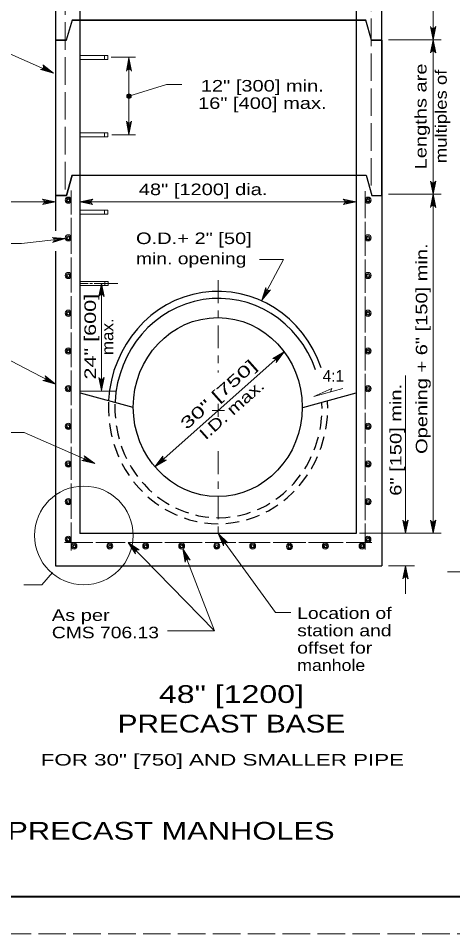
# Model space of a CAD drawing. Extents: x 808.4 to 842.4, y 1034.6 to 1056.6.
# Drawn here: x 819.97 to 825.84, y 1034.63 to 1047.01 of the extents above; entities that cross this region are included whole.
import ezdxf
from ezdxf.enums import TextEntityAlignment as Align

# ---------------------------------------------------------------- set-up
doc = ezdxf.new("R2010")
doc.units = 0
doc.header["$LTSCALE"] = 0.062
for name, pattern in [('DOT_DASHED', [7.7, 5, -1.2, 0.3, -1.2]), ('LONG_DASHED', [7.5, 6, -1.5]), ('MEDIUM_DASHED', [4.5, 3, -1.5])]:
    doc.linetypes.add(name, pattern=pattern)
doc.layers.add('1', color=7, linetype='Continuous', lineweight=13)
doc.layers.add('10', color=7, linetype='Continuous')

msp = doc.modelspace()

# ---------------------------------------------------------------- hatches: boundary and pattern name
at = {"layer": '1'}
msp.add_hatch(color=256, dxfattribs=at).paths.add_polyline_path([(821.49358, 1045.95525, 1), (821.43458, 1045.95525, 1)])

# ---------------------------------------------------------------- linework, layer by layer
at = {"layer": '1', "lineweight": 25}
for p, q in [((820.7995, 1049.0825), (820.7995, 1040.04192)), ((824.53808, 1049.0825), (824.53808, 1040.04192)), ((820.47083, 1048.75375), (820.47083, 1046.71117)), ((824.8835, 1046.71117), (824.88358, 1048.75375)), ((820.6975, 1046.98442), (824.66817, 1046.98442)), ((820.47083, 1046.71117), (820.47083, 1044.13583)), ((820.47083, 1046.71117), (820.61992, 1046.71117)), ((824.74583, 1046.71117), (824.88125, 1046.71117)), ((824.75008, 1046.71117), (824.88358, 1046.71117)), ((824.75008, 1046.71117), (824.8835, 1046.71117)), ((824.88358, 1046.71117), (824.88358, 1039.60358)), ((820.6975, 1044.88633), (824.6725, 1044.88633)), ((820.47083, 1043.85758), (820.47083, 1039.60358)), ((821.52008, 1041.74633), (820.80675, 1041.93983)), ((823.814, 1041.74633), (824.5355, 1041.942)), ((824.53942, 1040.04192), (820.7995, 1040.04192)), ((820.98625, 1040.04192), (820.7995, 1040.04192)), ((820.47083, 1039.60358), (824.88358, 1039.60358))]:
    msp.add_line(p, q, dxfattribs=at)
at = {"layer": '1', "linetype": 'LONG_DASHED'}
for p, q in [((824.74183, 1048.89308), (824.74183, 1044.64242)), ((820.59942, 1048.84225), (820.59942, 1044.61292))]:
    msp.add_line(p, q, dxfattribs=at)
at = {"layer": '1'}
for p, q in [((825.5775, 1048.75675), (825.5775, 1046.73775)), ((820.69325, 1046.98442), (820.61567, 1046.71117)), ((825.55508, 1046.87925), (825.5775, 1046.719)), ((825.56617, 1046.87383), (825.5775, 1046.719)), ((825.60233, 1046.88117), (825.5775, 1046.719)), ((825.59192, 1046.875), (825.5775, 1046.719)), ((825.5775, 1046.87217), (825.5775, 1046.719)), ((825.5775, 1046.80608), (825.5775, 1046.73242)), ((820.61625, 1046.71117), (820.48017, 1046.71117)), ((824.97292, 1046.71808), (825.68708, 1046.71808)), ((824.97292, 1046.71808), (825.68708, 1046.71808)), ((824.97292, 1046.71808), (825.68708, 1046.71808)), ((825.55275, 1046.55625), (825.5775, 1046.71833)), ((825.56317, 1046.56233), (825.5775, 1046.71833)), ((825.5775, 1046.56517), (825.5775, 1046.71833)), ((825.58883, 1046.56358), (825.5775, 1046.71833)), ((825.59992, 1046.55817), (825.5775, 1046.71833)), ((825.5775, 1046.70792), (825.5775, 1044.64733)), ((820.79992, 1046.50367), (821.178, 1046.50367)), ((820.79992, 1046.45058), (821.178, 1046.45058)), ((821.13425, 1046.4505), (821.13425, 1046.5035)), ((821.178, 1046.45058), (821.178, 1046.50367)), ((821.22425, 1046.48117), (821.553, 1046.48117)), ((821.43933, 1046.30958), (821.46408, 1046.47175)), ((821.44967, 1046.31575), (821.46408, 1046.47175)), ((821.46408, 1046.47175), (821.46408, 1045.43875)), ((821.46408, 1046.31858), (821.46408, 1046.47175)), ((821.47542, 1046.31692), (821.46408, 1046.47175)), ((821.4865, 1046.3115), (821.46408, 1046.47175)), ((820.28617, 1046.31842), (820.44242, 1046.26842)), ((820.29633, 1046.325), (820.44242, 1046.26842)), ((820.30525, 1046.33658), (820.44242, 1046.26842)), ((820.30883, 1046.3475), (820.44242, 1046.26842)), ((820.30892, 1046.35983), (820.44242, 1046.26842)), ((821.44167, 1045.599), (821.46408, 1045.43875)), ((821.45275, 1045.59358), (821.46408, 1045.43875)), ((821.48883, 1045.60092), (821.46408, 1045.43875)), ((821.4785, 1045.59475), (821.46408, 1045.43875)), ((821.46408, 1045.59192), (821.46408, 1045.43875)), ((820.79992, 1045.45742), (821.178, 1045.45742)), ((821.13425, 1045.40442), (821.13425, 1045.45742)), ((821.178, 1045.4045), (821.178, 1045.45742)), ((821.2325, 1045.43267), (821.553, 1045.43267)), ((820.79992, 1045.4045), (821.178, 1045.4045)), ((820.682, 1044.68158), (820.682, 1044.357)), ((825.55508, 1044.78883), (825.5775, 1044.62858)), ((825.56617, 1044.78342), (825.5775, 1044.62858)), ((825.60233, 1044.79075), (825.5775, 1044.62858)), ((825.59192, 1044.78458), (825.5775, 1044.62858)), ((825.5775, 1044.78175), (825.5775, 1044.62858)), ((820.62058, 1044.61308), (820.48442, 1044.61308)), ((824.65792, 1044.67175), (824.65792, 1044.30392)), ((824.74942, 1044.61308), (824.88358, 1044.61308)), ((824.97292, 1044.62767), (825.68708, 1044.62767)), ((825.55275, 1044.466), (825.5775, 1044.62817)), ((825.56317, 1044.47217), (825.5775, 1044.62817)), ((825.5775, 1044.475), (825.5775, 1044.62817)), ((825.58883, 1044.47333), (825.5775, 1044.62817)), ((825.59992, 1044.46792), (825.5775, 1044.62817)), ((825.5775, 1044.62767), (825.5775, 1040.04517)), ((820.47083, 1044.52517), (818.43792, 1044.52517)), ((820.30867, 1044.50042), (820.47083, 1044.52517)), ((820.31058, 1044.54758), (820.47083, 1044.52517)), ((820.31483, 1044.51083), (820.47083, 1044.52517)), ((820.316, 1044.5365), (820.47083, 1044.52517)), ((820.31767, 1044.52517), (820.47083, 1044.52517)), ((820.95975, 1044.54758), (820.7995, 1044.52517)), ((820.95433, 1044.5365), (820.7995, 1044.52517)), ((820.7995, 1044.52517), (823.3355, 1044.52517)), ((820.95267, 1044.52517), (820.7995, 1044.52517)), ((820.9555, 1044.51083), (820.7995, 1044.52517)), ((820.96158, 1044.50042), (820.7995, 1044.52517)), ((823.3355, 1044.52517), (824.53808, 1044.52517)), ((824.376, 1044.50042), (824.53808, 1044.52517)), ((824.37783, 1044.54758), (824.53808, 1044.52517)), ((824.38208, 1044.51083), (824.53808, 1044.52517)), ((824.38333, 1044.5365), (824.53808, 1044.52517)), ((824.38492, 1044.52517), (824.53808, 1044.52517)), ((820.682, 1044.30783), (820.682, 1043.82433)), ((820.79992, 1044.41125), (821.178, 1044.41125)), ((820.79992, 1044.35842), (821.178, 1044.35842)), ((821.13425, 1044.35858), (821.13425, 1044.4115)), ((821.178, 1044.35842), (821.178, 1044.41125)), ((824.65792, 1044.25475), (824.65792, 1043.79575)), ((820.43917, 1044.03683), (820.60308, 1044.0305)), ((820.44642, 1044.02717), (820.60308, 1044.0305)), ((820.44642, 1043.99008), (820.60308, 1044.0305)), ((820.4505, 1044.00175), (820.60308, 1044.0305)), ((820.45092, 1044.01317), (820.60308, 1044.0305)), ((820.682, 1043.77525), (820.682, 1043.29992)), ((824.65792, 1043.74667), (824.65792, 1043.29583)), ((820.80267, 1043.44967), (821.18067, 1043.44967)), ((821.13617, 1043.39708), (821.13617, 1043.45008)), ((821.18067, 1043.39667), (821.18067, 1043.44967)), ((820.80017, 1043.42325), (820.91392, 1043.42325)), ((820.80267, 1043.39667), (821.18067, 1043.39667)), ((820.93358, 1043.42325), (820.97233, 1043.42325)), ((820.99267, 1043.42325), (821.31308, 1043.42325)), ((821.06692, 1043.26092), (821.09175, 1043.423)), ((821.07733, 1043.267), (821.09175, 1043.423)), ((821.09175, 1043.423), (821.09175, 1041.974)), ((821.09175, 1043.26983), (821.09175, 1043.423)), ((821.10308, 1043.26817), (821.09175, 1043.423)), ((821.11417, 1043.26275), (821.09175, 1043.423)), ((823.31883, 1043.34733), (823.26333, 1043.19542)), ((823.32608, 1043.33733), (823.26333, 1043.19542)), ((823.33533, 1043.33058), (823.26333, 1043.19542)), ((823.36142, 1043.32683), (823.26333, 1043.19542)), ((823.34933, 1043.32633), (823.26333, 1043.19542)), ((820.682, 1043.25075), (820.682, 1042.80817)), ((824.65792, 1043.24667), (824.65792, 1042.75908)), ((820.682, 1042.75908), (820.682, 1042.29192)), ((824.65792, 1042.70992), (824.65792, 1042.24683)), ((821.81508, 1040.94158), (823.56483, 1042.49608)), ((823.42667, 1042.40767), (823.56483, 1042.49608)), ((823.43808, 1042.40392), (823.56483, 1042.49608)), ((823.44975, 1042.395), (823.56483, 1042.49608)), ((823.456, 1042.38533), (823.56483, 1042.49608)), ((823.45925, 1042.3735), (823.56483, 1042.49608)), ((820.682, 1042.24275), (820.682, 1041.77558)), ((820.31567, 1042.11167), (820.47083, 1042.05842)), ((820.32592, 1042.11808), (820.47083, 1042.05842)), ((820.33508, 1042.1295), (820.47083, 1042.05842)), ((820.33892, 1042.14033), (820.47083, 1042.05842)), ((820.33925, 1042.15267), (820.47083, 1042.05842)), ((821.06933, 1042.13425), (821.09175, 1041.974)), ((821.08042, 1042.12883), (821.09175, 1041.974)), ((821.1165, 1042.13617), (821.09175, 1041.974)), ((821.10608, 1042.13), (821.09175, 1041.974)), ((821.09175, 1042.12717), (821.09175, 1041.974)), ((824.65792, 1042.19767), (824.65792, 1041.72233)), ((825.20375, 1042.17908), (825.20375, 1040.04517)), ((820.81275, 1041.96708), (821.29075, 1041.96708)), ((823.96317, 1041.8935), (824.35825, 1042.00075)), ((820.682, 1041.7265), (820.682, 1041.26342)), ((822.58808, 1041.70475), (822.75533, 1041.70475)), ((822.67242, 1041.793), (822.67242, 1041.61742)), ((824.65792, 1041.67317), (824.65792, 1041.25933)), ((820.682, 1041.21425), (820.682, 1040.76758)), ((824.65792, 1041.21017), (824.65792, 1040.739)), ((820.84725, 1041.03158), (821.00275, 1040.98675)), ((820.85675, 1041.0395), (821.00275, 1040.98675)), ((820.86292, 1041.04917), (821.00275, 1040.98675)), ((820.86483, 1041.07542), (821.00275, 1040.98675)), ((820.86617, 1041.0635), (821.00275, 1040.98675)), ((821.92, 1041.06475), (821.81508, 1040.94158)), ((821.92325, 1041.05283), (821.81508, 1040.94158)), ((821.92958, 1041.04333), (821.81508, 1040.94158)), ((821.94125, 1041.03442), (821.81508, 1040.94158)), ((821.95275, 1041.03075), (821.81508, 1040.94158)), ((820.682, 1040.7185), (820.682, 1040.23908)), ((824.65792, 1040.68983), (824.65792, 1040.22267)), ((820.682, 1040.18992), (820.682, 1039.80892)), ((820.7995, 1040.16242), (820.7995, 1040.04192)), ((824.65792, 1040.1735), (824.65792, 1039.82383)), ((825.18133, 1040.20542), (825.20375, 1040.04517)), ((825.1925, 1040.2), (825.20375, 1040.04517)), ((825.22858, 1040.20733), (825.20375, 1040.04517)), ((825.21817, 1040.20117), (825.20375, 1040.04517)), ((825.20375, 1040.19833), (825.20375, 1040.04517)), ((825.55508, 1040.20542), (825.5775, 1040.04517)), ((825.56617, 1040.2), (825.5775, 1040.04517)), ((825.60233, 1040.20733), (825.5775, 1040.04517)), ((825.59192, 1040.20117), (825.5775, 1040.04517)), ((825.5775, 1040.19833), (825.5775, 1040.04517)), ((822.75808, 1039.915), (822.67242, 1040.04192)), ((822.77158, 1039.92067), (822.67242, 1040.04192)), ((822.78367, 1039.92142), (822.67242, 1040.04192)), ((822.74967, 1039.90725), (822.67242, 1040.04192)), ((822.7435, 1039.89658), (822.67242, 1040.04192)), ((822.67242, 1040.04192), (823.44675, 1038.97283)), ((824.53942, 1040.04192), (824.31883, 1040.04192)), ((824.58208, 1040.04517), (825.68708, 1040.04517)), ((820.9755, 1039.91742), (820.59367, 1039.91742)), ((821.41292, 1039.91742), (821.01425, 1039.91742)), ((821.91217, 1039.91742), (821.45167, 1039.91742)), ((821.56017, 1039.80942), (821.45167, 1039.91742)), ((821.57233, 1039.81758), (821.45167, 1039.91742)), ((821.584, 1039.82067), (821.45167, 1039.91742)), ((821.55333, 1039.80017), (821.45167, 1039.91742)), ((821.54942, 1039.7885), (821.45167, 1039.91742)), ((821.45167, 1039.91742), (822.61883, 1038.722)), ((822.454, 1039.91742), (821.95083, 1039.91742)), ((822.91067, 1039.91742), (822.49267, 1039.91742)), ((823.375, 1039.91742), (822.94933, 1039.91742)), ((823.855, 1039.91742), (823.41375, 1039.91742)), ((824.362, 1039.91742), (823.89367, 1039.91742)), ((824.75017, 1039.91742), (824.40067, 1039.91742)), ((822.24908, 1039.69008), (822.19058, 1039.83167)), ((822.26342, 1039.69292), (822.19058, 1039.83167)), ((822.27542, 1039.69125), (822.19058, 1039.83167)), ((822.23925, 1039.68425), (822.19058, 1039.83167)), ((822.23108, 1039.675), (822.19058, 1039.83167)), ((824.97292, 1039.60358), (825.32475, 1039.60358)), ((825.179, 1039.4415), (825.20375, 1039.60358)), ((825.18942, 1039.44758), (825.20375, 1039.60358)), ((825.20375, 1039.60358), (825.20375, 1039.22383)), ((825.20375, 1039.45042), (825.20375, 1039.60358)), ((825.21508, 1039.44883), (825.20375, 1039.60358)), ((825.22625, 1039.44333), (825.20375, 1039.60358)), ((825.77383, 1039.52317), (827.04975, 1039.52317)), ((823.44675, 1038.97283), (823.655, 1038.97283))]:
    msp.add_line(p, q, dxfattribs=at)
at = {"layer": '1', "linetype": 'DOT_DASHED'}
for p, q in [((822.67242, 1043.4655), (822.67242, 1042.2175)), ((822.67242, 1041.15467), (822.67242, 1040.04192))]:
    msp.add_line(p, q, dxfattribs=at)
at = {"layer": '1', "linetype": 'LONG_DASHED'}
msp.add_lwpolyline([(808.43883, 1034.62767), (842.43883, 1034.62767), (842.43883, 1056.62767), (808.43883, 1056.62767)], close=True, dxfattribs=at)
at = {"layer": '1', "lineweight": 25}
for points in [[(810.43883, 1056.12767), (841.93883, 1056.12767), (841.93883, 1035.12767), (810.43883, 1035.12767)], [(820.69325, 1046.98442), (820.61567, 1046.71117), (820.47083, 1046.71117), (820.47083, 1044.61308), (820.61992, 1044.61308), (820.6975, 1044.88633), (824.6725, 1044.88633), (824.75008, 1044.61308), (824.8835, 1044.61308), (824.88358, 1046.71117), (824.74583, 1046.71117), (824.66817, 1046.98442)]]:
    msp.add_lwpolyline(points, close=True, dxfattribs=at)
at = {"layer": '1', "lineweight": 40}
msp.add_lwpolyline([(810.43883, 1056.12767), (841.93883, 1056.12767), (841.93883, 1035.12767), (810.43883, 1035.12767)], close=True, dxfattribs=at)
at = {"layer": '1', "lineweight": 25}
for points in [[(820.69325, 1046.98442), (820.61567, 1046.71117), (820.47083, 1046.71117)], [(820.6975, 1044.88633), (820.61992, 1044.61308), (820.47083, 1044.61308)], [(824.6725, 1044.88633), (824.75008, 1044.61308), (824.8835, 1044.61308)]]:
    msp.add_lwpolyline(points, dxfattribs=at)
at = {"layer": '1'}
for points in [[(825.61292, 1046.896), (825.5775, 1046.719), (825.54217, 1046.896)], [(825.54217, 1046.54133), (825.5775, 1046.71833), (825.61292, 1046.54133)], [(820.44242, 1046.26842), (819.72975, 1046.58067), (819.50075, 1046.58067)], [(821.42867, 1046.29475), (821.46408, 1046.47175), (821.4995, 1046.29475)], [(820.26817, 1046.3155), (820.44242, 1046.26842), (820.29967, 1046.37892)], [(821.46408, 1045.95525), (821.96925, 1046.11392), (822.17908, 1046.11392)], [(821.4995, 1045.61575), (821.46408, 1045.43875), (821.42867, 1045.61575)], [(825.61292, 1044.80558), (825.5775, 1044.62858), (825.54217, 1044.80558)], [(820.29383, 1044.48983), (820.47083, 1044.52517), (820.29383, 1044.56058)], [(820.9765, 1044.48983), (820.7995, 1044.52517), (820.9765, 1044.56058)], [(824.36108, 1044.48983), (824.53808, 1044.52517), (824.36108, 1044.56058)], [(825.54217, 1044.45117), (825.5775, 1044.62817), (825.61292, 1044.45117)], [(820.60308, 1044.0305), (820.01208, 1043.96475), (819.82133, 1043.96475)], [(820.42325, 1044.04567), (820.60308, 1044.0305), (820.43117, 1043.97533)], [(823.26333, 1043.19542), (823.55575, 1043.74558), (823.22758, 1043.74558)], [(821.05633, 1043.246), (821.09175, 1043.423), (821.12717, 1043.246)], [(823.37775, 1043.335), (823.26333, 1043.19542), (823.31525, 1043.36825)], [(823.4085, 1042.40583), (823.56483, 1042.49608), (823.45517, 1042.35267)], [(820.47083, 1042.05842), (819.77183, 1042.42392), (819.52642, 1042.42392)], [(820.29758, 1042.10917), (820.47083, 1042.05842), (820.33042, 1042.17192)], [(821.12717, 1042.151), (821.09175, 1041.974), (821.05633, 1042.151)], [(823.96317, 1041.8935), (824.20992, 1042.00067), (824.18925, 1041.95442)], [(821.00275, 1040.98675), (820.04792, 1041.40742), (819.70025, 1041.40742)], [(820.85558, 1041.09125), (821.00275, 1040.98675), (820.82667, 1041.02658)], [(821.97092, 1041.03267), (821.81508, 1040.94158), (821.92392, 1041.08558)], [(825.23917, 1040.22217), (825.20375, 1040.04517), (825.16842, 1040.22217)], [(825.61292, 1040.22217), (825.5775, 1040.04517), (825.54217, 1040.22217)], [(822.80075, 1039.915), (822.67242, 1040.04192), (822.74208, 1039.87542)], [(821.60208, 1039.81767), (821.45167, 1039.91742), (821.55208, 1039.7675)], [(822.19058, 1039.83167), (822.61883, 1038.722), (821.98617, 1038.722)], [(822.29092, 1039.68158), (822.19058, 1039.83167), (822.22542, 1039.6545)], [(825.16842, 1039.42658), (825.20375, 1039.60358), (825.23917, 1039.42658)], [(820.42783, 1039.51225), (820.286, 1039.34492), (820.04183, 1039.34492)]]:
    msp.add_lwpolyline(points, dxfattribs=at)
for centre, radius in [((821.46408, 1045.95525), 0.0295), ((820.85329, 1040.01429), 0.66724)]:
    msp.add_circle(centre, radius, dxfattribs=at)
for centre, start, end in [((825.5775, 1046.91031), 202.08782, 337.91395), ((825.57757, 1046.52707), 22.08782, 157.91395), ((820.27113, 1046.35362), 265.65574, 41.48187), ((821.46412, 1046.28045), 22.08782, 157.91395), ((821.46404, 1045.63005), 202.08782, 337.91395), ((825.5775, 1044.8199), 202.08782, 337.91395), ((820.27952, 1044.52524), 292.08605, 67.91218), ((820.99077, 1044.52524), 112.08782, 247.91395), ((824.34682, 1044.52524), 292.08605, 67.91218), ((825.57757, 1044.43687), 22.08782, 157.91395), ((820.41301, 1044.00885), 298.57135, 74.39748), ((823.35321, 1043.36424), 174.04908, 309.87521), ((821.09177, 1043.23171), 22.08782, 157.91395), ((823.42112, 1042.36978), 333.38681, 109.21294), ((820.30135, 1042.14721), 264.45514, 40.28127), ((821.09169, 1042.16529), 202.08782, 337.91395), ((820.82806, 1041.06468), 268.03056, 43.85669), ((821.95806, 1041.06866), 153.70609, 289.53222), ((825.20375, 1040.23649), 202.08782, 337.91395), ((825.5775, 1040.23649), 202.08782, 337.91395), ((822.77938, 1039.88333), 56.08264, 191.90876), ((821.58719, 1039.78247), 67.22478, 203.05091), ((822.26358, 1039.65481), 44.5246, 180.35073), ((825.20383, 1039.41232), 22.08782, 157.91395)]:
    msp.add_arc(centre, 0.0382, start, end, dxfattribs=at)
for centre, major_axis in [((820.64222, 1044.54877), (0, 0.04232)), ((820.64152, 1044.5471), (0, -0.02865)), ((820.64348, 1044.54469), (0, -0.01649)), ((824.69843, 1044.54877), (0, 0.04232)), ((824.69914, 1044.5471), (0, -0.02865)), ((824.69718, 1044.54469), (0, -0.01649)), ((820.64222, 1044.03906), (0, 0.04232)), ((820.64152, 1044.03739), (0, -0.02865)), ((824.69843, 1044.03906), (0, 0.04232)), ((824.69914, 1044.03739), (0, -0.02865)), ((820.64348, 1044.03498), (0, -0.01649)), ((824.69718, 1044.03498), (0, -0.01649)), ((820.64222, 1043.52935), (0, 0.04232)), ((824.69843, 1043.52935), (0, 0.04232)), ((820.64152, 1043.52769), (0, -0.02865)), ((820.64348, 1043.52527), (0, -0.01649)), ((824.69914, 1043.52769), (0, -0.02865)), ((824.69718, 1043.52527), (0, -0.01649)), ((820.64222, 1043.01965), (0, 0.04232)), ((820.64152, 1043.01798), (0, -0.02865)), ((820.64348, 1043.01557), (0, -0.01649)), ((824.69843, 1043.01965), (0, 0.04232)), ((824.69914, 1043.01798), (0, -0.02865)), ((824.69718, 1043.01557), (0, -0.01649)), ((820.64222, 1042.50994), (0, 0.04232)), ((820.64152, 1042.50828), (0, -0.02865)), ((820.64348, 1042.50586), (0, -0.01649)), ((824.69843, 1042.50994), (0, 0.04232)), ((824.69914, 1042.50828), (0, -0.02865)), ((824.69718, 1042.50586), (0, -0.01649)), ((820.64222, 1042.00023), (0, 0.04232)), ((820.64152, 1041.99857), (0, -0.02865)), ((820.64348, 1041.99615), (0, -0.01649)), ((824.69843, 1042.00023), (0, 0.04232)), ((824.69914, 1041.99857), (0, -0.02865)), ((824.69718, 1041.99615), (0, -0.01649)), ((820.64222, 1041.49053), (0, 0.04232)), ((820.64152, 1041.48886), (0, -0.02865)), ((820.64348, 1041.48645), (0, -0.01649)), ((824.69843, 1041.49053), (0, 0.04232)), ((824.69914, 1041.48886), (0, -0.02865)), ((824.69718, 1041.48645), (0, -0.01649)), ((820.64222, 1040.98082), (0, 0.04232)), ((820.64152, 1040.97916), (0, -0.02865)), ((820.64348, 1040.97674), (0, -0.01649)), ((824.69843, 1040.98082), (0, 0.04232)), ((824.69914, 1040.97916), (0, -0.02865)), ((824.69718, 1040.97674), (0, -0.01649)), ((820.64222, 1040.47112), (0, 0.04232)), ((820.64152, 1040.46945), (0, -0.02865)), ((820.64348, 1040.46703), (0, -0.01649)), ((824.69843, 1040.47112), (0, 0.04232)), ((824.69914, 1040.46945), (0, -0.02865)), ((824.69718, 1040.46703), (0, -0.01649)), ((820.64222, 1039.96141), (0, 0.04232)), ((820.64152, 1039.95974), (0, -0.02865)), ((820.64348, 1039.95733), (0, -0.01649)), ((824.69725, 1039.96141), (0, 0.04232)), ((824.69615, 1039.96174), (0, -0.02865)), ((824.69812, 1039.95933), (0, -0.01649)), ((820.72065, 1039.87113), (0, 0.04232)), ((820.72089, 1039.87071), (0, -0.02865)), ((820.72286, 1039.8683), (0, -0.01649)), ((821.2039, 1039.87113), (0, 0.04232)), ((821.20351, 1039.87071), (0, -0.02865)), ((821.20548, 1039.8683), (0, -0.01649)), ((821.69006, 1039.87113), (0, 0.04232)), ((821.68849, 1039.87071), (0, -0.02865)), ((821.69046, 1039.8683), (0, -0.01649)), ((822.17622, 1039.87113), (0, 0.04232)), ((822.17449, 1039.87071), (0, -0.02865)), ((822.17646, 1039.8683), (0, -0.01649)), ((822.6509, 1039.87113), (0, 0.04232)), ((822.65011, 1039.87005), (0, -0.02865)), ((822.65208, 1039.86763), (0, -0.01649)), ((823.13706, 1039.87113), (0, 0.04232)), ((823.13682, 1039.87129), (0, -0.02865)), ((823.13879, 1039.86888), (0, -0.01649)), ((823.63478, 1039.86505), (0, 0.04232)), ((823.63596, 1039.86446), (0, -0.02865)), ((823.63793, 1039.86205), (0, -0.01649)), ((824.12086, 1039.87113), (0, 0.04232)), ((824.12165, 1039.87079), (0, -0.02865)), ((824.12362, 1039.86838), (0, -0.01649)), ((824.61631, 1039.87263), (0, 0.04232)), ((824.61741, 1039.87338), (0, -0.02865)), ((824.61937, 1039.87096), (0, -0.01649))]:
    msp.add_ellipse(centre, major_axis=major_axis, ratio=0.944544, dxfattribs=at)
at = {"layer": '1', "lineweight": 25}
for centre, major_axis, start_param, end_param in [((822.66861, 1041.7442), (0, 1.57124), 5.05957511, 7.79178954), ((822.67458, 1041.73702), (0, 1.48364), 5.06755757, 7.79799099)]:
    msp.add_ellipse(centre, major_axis=major_axis, ratio=0.944544, start_param=start_param, end_param=end_param, dxfattribs=at)
msp.add_ellipse((822.66467, 1041.75071), major_axis=(0, 1.20985), ratio=0.944544, dxfattribs=at)
at = {"layer": '1', "linetype": 'MEDIUM_DASHED', "lineweight": 25}
for centre, major_axis, start_param, end_param in [((822.66861, 1041.7442), (0, 1.57124), 1.52605103, 4.76713962), ((822.67458, 1041.73702), (0, 1.48364), 1.53664377, 4.75717553)]:
    msp.add_ellipse(centre, major_axis=major_axis, ratio=0.944544, start_param=start_param, end_param=end_param, dxfattribs=at)

# ---------------------------------------------------------------- texts
at = {"layer": '1'}
for s, width, p in [('Location of', 1.25, (823.73967, 1038.88517)), ('station and', 1.25, (823.73967, 1038.6505)), ('offset for', 1.25, (823.73967, 1038.41583)), ('manhole', 1.15, (823.73967, 1038.18117))]:
    msp.add_text(s, height=0.156, dxfattribs=dict(at, width=width)).set_placement(p)
at = {"layer": '10'}
for s, rotation, width, p in [('Lengths are', 90, 1.3, (825.48875, 1045.68096)), ('multiples of', 90, 1.2, (825.76275, 1045.68096)), ('24" [600]', 90, 1.4, (821.01708, 1042.70204)), ('max.', 90, 1.1, (821.25175, 1042.702)), ('30" [750]', 41.617, 1.55, (822.72445, 1041.86329)), ('I.D. max.', 41.617, 1.3, (822.90645, 1041.65852)), ('6" [150] min.', 90, 1.3, (825.14992, 1041.30737))]:
    msp.add_text(s, height=0.156, rotation=rotation, dxfattribs=dict(at, width=width)).set_placement(p, align=Align.CENTER)
for s, height, width, p in [('12" [300] min.', 0.156, 1.3, (823.26746, 1046.01792)), ('16" [400] max.', 0.156, 1.3, (823.26742, 1045.78325)), ('48" [1200]', 0.24, 1.35, (822.84971, 1037.74867)), ('PRECAST BASE', 0.24, 1.25, (822.84962, 1037.34867))]:
    msp.add_text(s, height=height, dxfattribs=dict(at, width=width)).set_placement(p, align=Align.CENTER)
for s, height, width, p in [('48" [1200] dia.', 0.156, 1.3, (821.59683, 1044.61683)), ('O.D.+ 2" [50]', 0.156, 1.3, (821.55917, 1043.955)), ('min. opening', 0.156, 1.25, (821.55917, 1043.681)), ('As per', 0.156, 1.3, (820.42017, 1038.85808)), ('CMS 706.13', 0.156, 1.25, (820.42017, 1038.62342)), ('FOR 30" [750] AND SMALLER PIPE', 0.156, 1.45, (820.26967, 1036.90175)), ('SECTION VIEWS OF REINFORCED PRECAST MANHOLES', 0.24, 1.3, (812.81725, 1035.89925))]:
    msp.add_text(s, height=height, dxfattribs=dict(at, width=width)).set_placement(p)
at = {"layer": '10', "width": 1.3}
msp.add_text('Opening + 6" [150] min.', height=0.156, rotation=90, dxfattribs=at).set_placement((825.50017, 1041.11667))
at = {"layer": '10'}
msp.add_text('4:1', height=0.156, dxfattribs=at).set_placement((824.084, 1042.09367))

doc.saveas('drawing.dxf')
